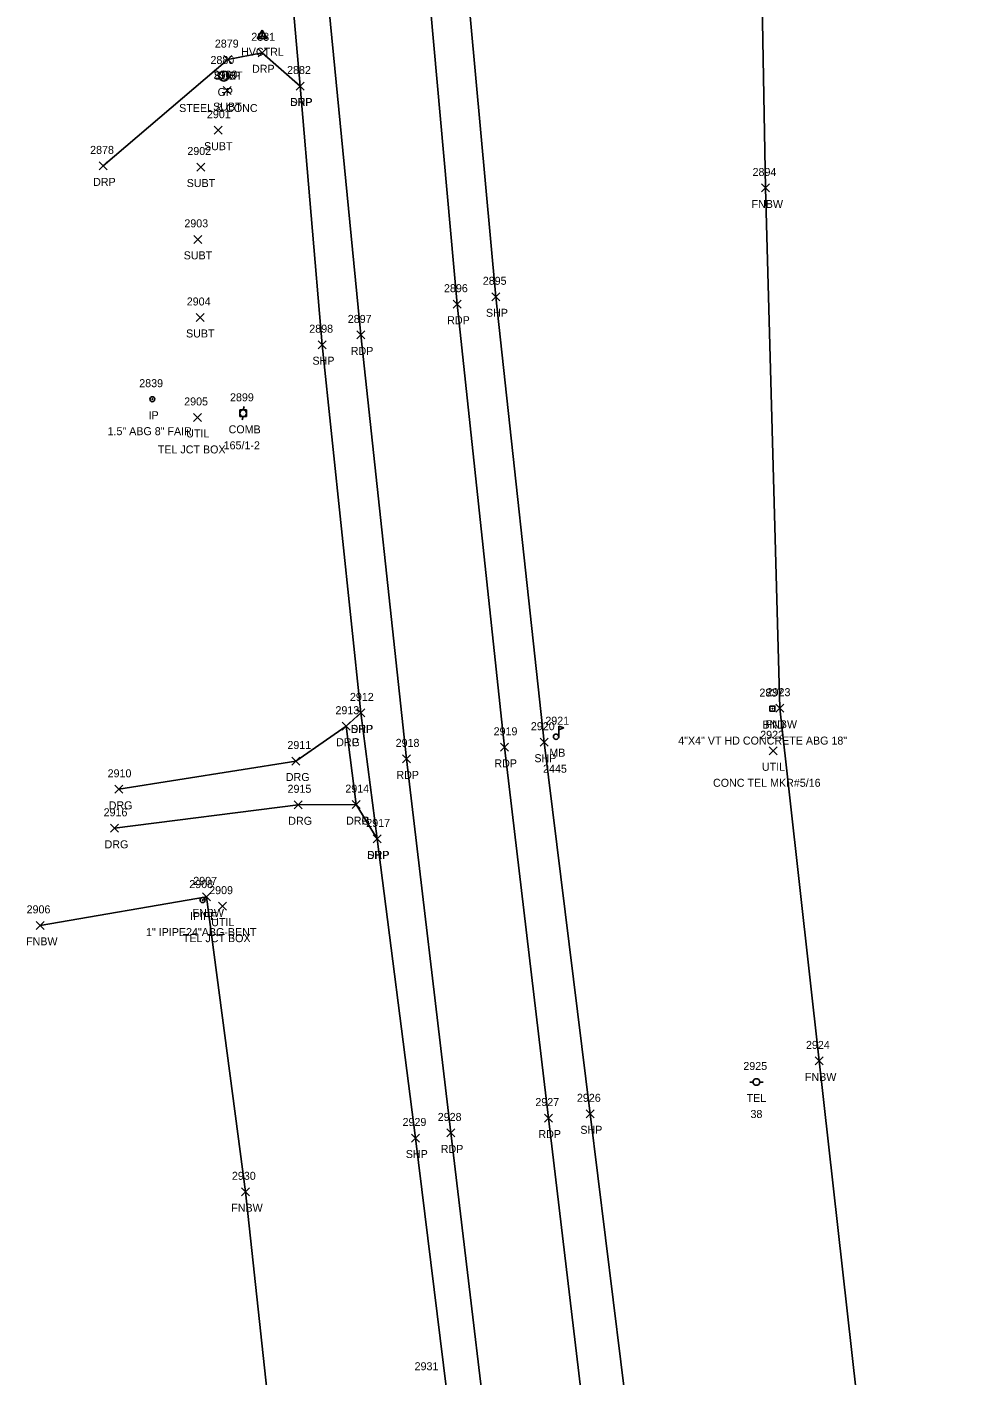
# Model space of a CAD drawing. Extents: x 1443071 to 1445292, y 614024 to 622563.
# Drawn here: x 1443962.9 to 1444198.2, y 618886.1 to 619223.1 of the extents above; entities that cross this region are included whole.
import ezdxf

# ---------------------------------------------------------------- set-up
doc = ezdxf.new("R2010")
doc.units = 0
for name, color, linetype in [('C_A', 7, 'Continuous'), ('CPSM', 7, 'Continuous'), ('L_A', 7, 'Continuous'), ('L_C', 7, 'Continuous'), ('L_I', 7, 'Continuous'), ('L_TIC', 7, 'Continuous'), ('LFNC', 7, 'Continuous'), ('LMB', 7, 'Continuous'), ('M_A', 7, 'Continuous'), ('M_C', 7, 'Continuous'), ('M_I', 7, 'Continuous'), ('MHBP', 7, 'Continuous'), ('MPIP', 7, 'Continuous'), ('MPIR', 7, 'Continuous'), ('P_A', 7, 'Continuous'), ('P_I', 7, 'Continuous'), ('P_TIC', 7, 'Continuous'), ('PET', 7, 'Continuous'), ('PSP', 7, 'Continuous'), ('R_A', 7, 'Continuous'), ('R_C', 7, 'Continuous'), ('R_I', 7, 'Continuous'), ('R_TIC', 7, 'Continuous'), ('RDG', 7, 'Continuous'), ('RDP', 7, 'Continuous'), ('RGP', 7, 'Continuous'), ('S_I', 7, 'Continuous'), ('U_A', 7, 'Continuous'), ('U_C', 7, 'Continuous'), ('U_I', 7, 'Continuous'), ('U_TIC', 7, 'Continuous'), ('UDEFAULT', 7, 'Continuous'), ('UP', 7, 'Continuous')]:
    doc.layers.add(name, color=color, linetype=linetype)

msp = doc.modelspace()

# ---------------------------------------------------------------- linework, layer by layer
at = {"layer": 'CPSM'}
for p, q in [((1444020.47, 619220.14), (1444021.72, 619222.3)), ((1444020.47, 619220.14), (1444021.72, 619220.86)), ((1444020.47, 619220.14), (1444022.97, 619220.14)), ((1444022.97, 619220.14), (1444021.72, 619222.3)), ((1444021.72, 619220.86), (1444021.72, 619222.3)), ((1444021.72, 619220.86), (1444021.72, 619220.86)), ((1444021.72, 619220.86), (1444022.97, 619220.14))]:
    msp.add_line(p, q, dxfattribs=at)
at = {"layer": 'L_TIC'}
for points in [[(1444146.59, 619181.81), (1444148.59, 619183.81)], [(1444148.59, 619181.81), (1444146.59, 619183.81)], [(1444150.11, 619051.76), (1444152.11, 619053.76)], [(1444152.11, 619051.76), (1444150.11, 619053.76)], [(1444006.8, 619004.6), (1444008.8, 619006.6)], [(1444008.8, 619004.6), (1444006.8, 619006.6)], [(1443965.17, 618997.47), (1443967.17, 618999.47)], [(1443967.17, 618997.47), (1443965.17, 618999.47)], [(1444159.95, 618963.58), (1444161.95, 618965.58)], [(1444161.95, 618963.58), (1444159.95, 618965.58)], [(1444016.48, 618930.86), (1444018.48, 618932.86)], [(1444018.48, 618930.86), (1444016.48, 618932.86)]]:
    msp.add_lwpolyline(points, dxfattribs=at)
at = {"layer": 'LFNC'}
for points in [[(1444140.95, 619617.62), (1444141.66, 619543.48), (1444143.47, 619453.28), (1444144.69, 619378.28), (1444145.89, 619275.11), (1444147.59, 619182.81), (1444151.11, 619052.76), (1444160.95, 618964.58), (1444173.83, 618850.02), (1444185.25, 618752.69), (1444198.22, 618656.01)], [(1443966.17, 618998.47), (1444007.8, 619005.6), (1444017.48, 618931.86), (1444028.26, 618832.25), (1444038.4, 618732.12), (1444049.1, 618629.72), (1444058.56, 618539.25), (1444065.36, 618471.37), (1444074.33, 618387.05), (1444083.93, 618296.19)]]:
    msp.add_lwpolyline(points, dxfattribs=at)
at = {"layer": 'LMB'}
for p, q in [((1444095.84, 619048.23), (1444097.14, 619047.85)), ((1444095.85, 619045.64), (1444095.85, 619048.23)), ((1444095.19, 619045.63), (1444095.19, 619045.63)), ((1444095.85, 619047.33), (1444097.13, 619047.84))]:
    msp.add_line(p, q, dxfattribs=at)
msp.add_circle((1444095.19, 619045.63), 0.656, dxfattribs=at)
at = {"layer": 'MHBP'}
msp.add_lwpolyline([(1444148.67, 619053.28), (1444149.92, 619053.28), (1444149.92, 619052.03), (1444148.67, 619052.03)], close=True, dxfattribs=at)
msp.add_circle((1444149.3, 619052.66), 0.0833, dxfattribs=at)
at = {"layer": 'MPIP'}
for radius in [0.625, 0.0833]:
    msp.add_circle((1444006.8, 619004.79), radius, dxfattribs=at)
at = {"layer": 'MPIR'}
for radius in [0.625, 0.0833]:
    msp.add_circle((1443994.22, 619130.01), radius, dxfattribs=at)
at = {"layer": 'P_TIC'}
for points in [[(1444030.18, 619207.3), (1444032.18, 619209.3)], [(1444032.18, 619207.3), (1444030.18, 619209.3)], [(1444079.12, 619154.61), (1444081.12, 619156.61)], [(1444081.12, 619154.61), (1444079.12, 619156.61)], [(1444069.47, 619152.76), (1444071.47, 619154.76)], [(1444071.47, 619152.76), (1444069.47, 619154.76)], [(1444045.36, 619145.08), (1444047.36, 619147.08)], [(1444047.36, 619145.08), (1444045.36, 619147.08)], [(1444035.73, 619142.63), (1444037.73, 619144.63)], [(1444037.73, 619142.63), (1444035.73, 619144.63)], [(1444045.33, 619050.58), (1444047.33, 619052.58)], [(1444047.33, 619050.58), (1444045.33, 619052.58)], [(1444091.23, 619043.26), (1444093.23, 619045.26)], [(1444093.23, 619043.26), (1444091.23, 619045.26)], [(1444081.27, 619041.98), (1444083.27, 619043.98)], [(1444083.27, 619041.98), (1444081.27, 619043.98)], [(1444056.76, 619039.09), (1444058.76, 619041.09)], [(1444058.76, 619039.09), (1444056.76, 619041.09)], [(1444049.41, 619019.07), (1444051.41, 619021.07)], [(1444051.41, 619019.07), (1444049.41, 619021.07)], [(1444092.27, 618949.3), (1444094.27, 618951.3)], [(1444094.27, 618949.3), (1444092.27, 618951.3)], [(1444102.72, 618950.36), (1444104.72, 618952.36)], [(1444104.72, 618950.36), (1444102.72, 618952.36)], [(1444067.86, 618945.58), (1444069.86, 618947.58)], [(1444069.86, 618945.58), (1444067.86, 618947.58)], [(1444059.07, 618944.31), (1444061.07, 618946.31)], [(1444061.07, 618944.31), (1444059.07, 618946.31)]]:
    msp.add_lwpolyline(points, dxfattribs=at)
at = {"layer": 'PET'}
for points in [[(1444060.23, 619757.24), (1444030.6, 619759.6), (1444027.22, 619690.19), (1444024.14, 619595.2), (1444026, 619550.02), (1444025.36, 619470.06), (1444027.67, 619387.44), (1444035.05, 619262.29), (1444046.36, 619146.08), (1444057.76, 619040.09), (1444068.86, 618946.58), (1444081.65, 618839.75), (1444094.51, 618740.27), (1444109.49, 618620.85), (1444119.47, 618545.62)], [(1444060.23, 619757.24), (1444055.7, 619686.84), (1444052.09, 619593.54), (1444051.88, 619548.79), (1444051.53, 619469.84), (1444057.39, 619386.89), (1444060.43, 619264.84), (1444070.47, 619153.76), (1444082.27, 619042.98), (1444093.27, 618950.3), (1444106.23, 618841.72), (1444119.2, 618742.75), (1444134.15, 618623.05), (1444144.16, 618546.64)]]:
    msp.add_lwpolyline(points, dxfattribs=at)
at = {"layer": 'PSP'}
for points in [[(1444030.6, 619759.6), (1444029.33, 619753.09), (1444025.71, 619690.24), (1444018.62, 619596.21), (1444016.49, 619550.78), (1444015.83, 619506.94), (1444016.35, 619478.84), (1444019.52, 619385.97), (1444025.45, 619273.62), (1444031.18, 619208.3), (1444036.73, 619143.63), (1444046.33, 619051.58), (1444050.41, 619020.07), (1444060.07, 618945.31), (1444073.2, 618838.48), (1444085.76, 618739.52), (1444101.61, 618620.44), (1444111.35, 618544.8)], [(1444060.23, 619757.24), (1444060.46, 619750.33), (1444058.96, 619686.98), (1444059.06, 619593.34), (1444060.01, 619548.92), (1444060.2, 619469.56), (1444062.86, 619388.02), (1444070.04, 619265.9), (1444080.12, 619155.61), (1444092.23, 619044.26), (1444103.72, 618951.36), (1444117.15, 618842.88), (1444129.88, 618744.38), (1444144.78, 618624.26), (1444154.69, 618549.98)]]:
    msp.add_lwpolyline(points, dxfattribs=at)
at = {"layer": 'R_TIC'}
for points in [[(1444020.67, 619215.6), (1444022.67, 619217.6)], [(1444022.67, 619215.6), (1444020.67, 619217.6)], [(1444012.13, 619213.91), (1444014.13, 619215.91)], [(1444014.13, 619213.91), (1444012.13, 619215.91)], [(1444030.18, 619207.3), (1444032.18, 619209.3)], [(1444032.18, 619207.3), (1444030.18, 619209.3)], [(1443980.93, 619187.33), (1443982.93, 619189.33)], [(1443982.93, 619187.33), (1443980.93, 619189.33)], [(1444045.33, 619050.58), (1444047.33, 619052.58)], [(1444047.33, 619050.58), (1444045.33, 619052.58)], [(1444041.71, 619047.26), (1444043.71, 619049.26)], [(1444043.71, 619047.26), (1444041.71, 619049.26)], [(1444041.71, 619047.26), (1444043.71, 619049.26)], [(1444043.71, 619047.26), (1444041.71, 619049.26)], [(1444029.12, 619038.55), (1444031.12, 619040.55)], [(1444031.12, 619038.55), (1444029.12, 619040.55)], [(1443984.82, 619031.48), (1443986.82, 619033.48)], [(1443986.82, 619031.48), (1443984.82, 619033.48)], [(1444029.73, 619027.61), (1444031.73, 619029.61)], [(1444031.73, 619027.61), (1444029.73, 619029.61)], [(1444044.18, 619027.65), (1444046.18, 619029.65)], [(1444046.18, 619027.65), (1444044.18, 619029.65)], [(1444044.18, 619027.65), (1444046.18, 619029.65)], [(1444046.18, 619027.65), (1444044.18, 619029.65)], [(1443983.79, 619021.73), (1443985.79, 619023.73)], [(1443985.79, 619021.73), (1443983.79, 619023.73)], [(1444049.41, 619019.07), (1444051.41, 619021.07)], [(1444051.41, 619019.07), (1444049.41, 619021.07)]]:
    msp.add_lwpolyline(points, dxfattribs=at)
at = {"layer": 'RDG'}
for points in [[(1443985.82, 619032.48), (1444030.12, 619039.55), (1444042.71, 619048.26)], [(1444045.18, 619028.65), (1444030.73, 619028.61), (1443984.79, 619022.73)]]:
    msp.add_lwpolyline(points, dxfattribs=at)
at = {"layer": 'RDP'}
for points in [[(1443981.93, 619188.33), (1444013.13, 619214.91), (1444021.67, 619216.6), (1444031.18, 619208.3)], [(1444046.33, 619051.58), (1444042.71, 619048.26), (1444045.18, 619028.65), (1444050.41, 619020.07)]]:
    msp.add_lwpolyline(points, dxfattribs=at)
at = {"layer": 'RGP'}
msp.add_line((1444012.1, 619210.8), (1444012.1, 619210.8), dxfattribs=at)
for radius in [1.25, 0.0833]:
    msp.add_circle((1444012.1, 619210.8), radius, dxfattribs=at)
at = {"layer": 'U_TIC'}
for points in [[(1444012.13, 619213.91), (1444014.13, 619215.91)], [(1444014.13, 619213.91), (1444012.13, 619215.91)], [(1444011.93, 619206.15), (1444013.93, 619208.15)], [(1444013.93, 619206.15), (1444011.93, 619208.15)], [(1444009.65, 619196.26), (1444011.65, 619198.26)], [(1444011.65, 619196.26), (1444009.65, 619198.26)], [(1444005.32, 619187.05), (1444007.32, 619189.05)], [(1444007.32, 619187.05), (1444005.32, 619189.05)], [(1444004.56, 619168.97), (1444006.56, 619170.97)], [(1444006.56, 619168.97), (1444004.56, 619170.97)], [(1444005.17, 619149.44), (1444007.17, 619151.44)], [(1444007.17, 619149.44), (1444005.17, 619151.44)]]:
    msp.add_lwpolyline(points, dxfattribs=at)
at = {"layer": 'UDEFAULT'}
for points in [[(1444004.53, 619124.45), (1444006.53, 619126.45)], [(1444006.53, 619124.45), (1444004.53, 619126.45)], [(1444148.5, 619041.11), (1444150.5, 619043.11)], [(1444150.5, 619041.11), (1444148.5, 619043.11)], [(1444010.78, 619002.27), (1444012.78, 619004.27)], [(1444012.78, 619002.27), (1444010.78, 619004.27)]]:
    msp.add_lwpolyline(points, dxfattribs=at)
at = {"layer": 'UP'}
for p, q in [((1444016.09, 619125.65), (1444016.09, 619127.31)), ((1444016.09, 619127.31), (1444017.75, 619127.31)), ((1444017.17, 619128.15), (1444016.92, 619127.31)), ((1444016.92, 619126.48), (1444016.92, 619126.48)), ((1444017.75, 619127.31), (1444017.75, 619125.65)), ((1444017.75, 619125.65), (1444016.09, 619125.65)), ((1444016.67, 619124.81), (1444016.92, 619125.65)), ((1444143.62, 618959.31), (1444144.44, 618959.31)), ((1444145.28, 618959.31), (1444145.28, 618959.31)), ((1444146.94, 618959.31), (1444146.11, 618959.31)), ((1444146.11, 618959.31), (1444146.11, 618959.31)), ((1444146.94, 618959.31), (1444146.94, 618959.31))]:
    msp.add_line(p, q, dxfattribs=at)
for centre in [(1444016.92, 619126.48), (1444145.28, 618959.31)]:
    msp.add_circle(centre, 0.833, dxfattribs=at)

# ---------------------------------------------------------------- texts
at = {"layer": 'C_A'}
msp.add_text('HVCTRL', height=2, dxfattribs=at).set_placement((1444016.41, 619215.86))
at = {"layer": 'L_A'}
for s, p in [('FNBW', (1444144.07, 619177.81)), ('FNBW', (1444147.58, 619047.76)), ('MB', (1444093.5, 619040.63)), ('FNBW', (1444004.27, 619000.6)), ('FNBW', (1443962.65, 618993.47)), ('FNBW', (1444157.42, 618959.58)), ('FNBW', (1444013.95, 618926.86))]:
    msp.add_text(s, height=2, dxfattribs=at).set_placement(p)
at = {"layer": 'L_C'}
msp.add_text('2445', height=2, dxfattribs=at).set_placement((1444091.93, 619036.63))
at = {"layer": 'L_I'}
for s, p in [('2894', (1444144.33, 619185.81)), ('2923', (1444147.85, 619055.76)), ('2921', (1444092.5, 619048.63)), ('2907', (1444004.46, 619008.6)), ('2906', (1443962.78, 619001.47)), ('2924', (1444157.69, 618967.58)), ('2930', (1444014.13, 618934.86))]:
    msp.add_text(s, height=2, dxfattribs=at).set_placement(p)
at = {"layer": 'M_A'}
for s, p in [('IP', (1443993.27, 619125.01)), ('BND', (1444146.79, 619047.66)), ('IPIPE', (1444003.64, 618999.79))]:
    msp.add_text(s, height=2, dxfattribs=at).set_placement(p)
at = {"layer": 'M_C'}
for s, p in [('1.5" ABG 8" FAIR', (1443983.02, 619121.01)), ('4"X4" VT HD CONCRETE ABG 18"', (1444125.74, 619043.66)), ('1" IPIPE24"ABG-BENT', (1443992.64, 618995.79))]:
    msp.add_text(s, height=2, dxfattribs=at).set_placement(p)
at = {"layer": 'M_I'}
for s, p in [('2839', (1443990.95, 619133.01)), ('2837', (1444146.04, 619055.66)), ('2908', (1444003.46, 619007.79))]:
    msp.add_text(s, height=2, dxfattribs=at).set_placement(p)
at = {"layer": 'P_A'}
for s, p in [('SHP', (1444028.71, 619203.3)), ('RDP', (1444067.96, 619148.76)), ('SHP', (1444077.65, 619150.61)), ('RDP', (1444043.85, 619141.08)), ('SHP', (1444034.27, 619138.63)), ('SHP', (1444043.87, 619046.58)), ('RDP', (1444079.76, 619037.98)), ('SHP', (1444089.77, 619039.26)), ('RDP', (1444055.25, 619035.09)), ('SHP', (1444047.94, 619015.07)), ('RDP', (1444090.76, 618945.3)), ('SHP', (1444101.26, 618946.36)), ('SHP', (1444057.61, 618940.31)), ('RDP', (1444066.35, 618941.58))]:
    msp.add_text(s, height=2, dxfattribs=at).set_placement(p)
at = {"layer": 'P_I'}
for s, p in [('2882', (1444027.92, 619211.3)), ('2895', (1444076.86, 619158.61)), ('2896', (1444067.16, 619156.76)), ('2897', (1444043.1, 619149.08)), ('2898', (1444033.47, 619146.63)), ('2912', (1444043.64, 619054.58)), ('2920', (1444088.89, 619047.26)), ('2918', (1444055.07, 619043.09)), ('2919', (1444079.57, 619045.98)), ('2917', (1444047.72, 619023.07)), ('2927', (1444090.01, 618953.3)), ('2926', (1444100.41, 618954.36)), ('2928', (1444065.6, 618949.58)), ('2929', (1444056.8, 618948.31))]:
    msp.add_text(s, height=2, dxfattribs=at).set_placement(p)
at = {"layer": 'R_A'}
for s, p in [('DRP', (1444019.15, 619211.6)), ('DRP', (1444010.61, 619209.91)), ('GP', (1444010.54, 619205.8)), ('DRP', (1444028.66, 619203.3)), ('DRP', (1443979.41, 619183.33)), ('DRP', (1444043.82, 619046.58)), ('DRG', (1444040.2, 619043.26)), ('DRP', (1444040.2, 619043.26)), ('DRG', (1444027.61, 619034.55)), ('DRG', (1443983.31, 619027.48)), ('DRG', (1444028.22, 619023.61)), ('DRG', (1444042.67, 619023.65)), ('DRP', (1444042.67, 619023.65)), ('DRG', (1443982.28, 619017.73)), ('DRP', (1444047.9, 619015.07))]:
    msp.add_text(s, height=2, dxfattribs=at).set_placement(p)
at = {"layer": 'R_C'}
msp.add_text('STEEL & CONC', height=2, dxfattribs=at).set_placement((1444000.93, 619201.8))
at = {"layer": 'R_I'}
for s, p in [('2881', (1444018.97, 619219.6)), ('2879', (1444009.86, 619217.91)), ('2880', (1444008.76, 619213.8)), ('2882', (1444027.92, 619211.3)), ('2878', (1443978.67, 619191.33)), ('2912', (1444043.64, 619054.58)), ('2913', (1444040.02, 619051.26)), ('2913', (1444040.02, 619051.26)), ('2911', (1444028, 619042.55)), ('2910', (1443983.04, 619035.48)), ('2915', (1444028.04, 619031.61)), ('2914', (1444042.49, 619031.65)), ('2914', (1444042.49, 619031.65)), ('2916', (1443982.04, 619025.73)), ('2917', (1444047.72, 619023.07))]:
    msp.add_text(s, height=2, dxfattribs=at).set_placement(p)
at = {"layer": 'S_I'}
msp.add_text('2931', height=2, dxfattribs=at).set_placement((1444059.81, 618887.25))
at = {"layer": 'U_A'}
for s, p in [('SUBT', (1444009.62, 619209.91)), ('SUBT', (1444009.43, 619202.15)), ('SUBT', (1444007.15, 619192.26)), ('SUBT', (1444002.82, 619183.05)), ('SUBT', (1444002.06, 619164.97)), ('SUBT', (1444002.66, 619145.44)), ('UTIL', (1444002.7, 619120.45)), ('COMB', (1444013.3, 619121.48)), ('UTIL', (1444146.67, 619037.11)), ('UTIL', (1444008.95, 618998.27)), ('TEL', (1444142.84, 618954.31))]:
    msp.add_text(s, height=2, dxfattribs=at).set_placement(p)
at = {"layer": 'U_C'}
for s, p in [('165/1-2', (1444012.05, 619117.48)), ('TEL JCT BOX', (1443995.59, 619116.45)), ('CONC TEL MKR#5/16', (1444134.44, 619033.11)), ('TEL JCT BOX', (1444001.85, 618994.27)), ('38', (1444143.81, 618950.31))]:
    msp.add_text(s, height=2, dxfattribs=at).set_placement(p)
at = {"layer": 'U_I'}
for s, p in [('2879', (1444009.86, 619217.91)), ('2900', (1444009.51, 619210.15)), ('2901', (1444007.88, 619200.26)), ('2902', (1444002.98, 619191.05)), ('2903', (1444002.23, 619172.97)), ('2904', (1444002.83, 619153.44)), ('2905', (1444002.19, 619128.45)), ('2899', (1444013.65, 619129.48)), ('2922', (1444146.24, 619045.11)), ('2909', (1444008.44, 619006.27)), ('2925', (1444142.02, 618962.31))]:
    msp.add_text(s, height=2, dxfattribs=at).set_placement(p)

doc.saveas('drawing.dxf')
